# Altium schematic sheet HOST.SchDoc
size 431 x 279 mm; SheetNumber: 4; SheetTotal: 4; ENG_APP_DATE: --/--/--; DSN_APP_DATE: --/--/--; CHK_APP_DATE: --/--/--
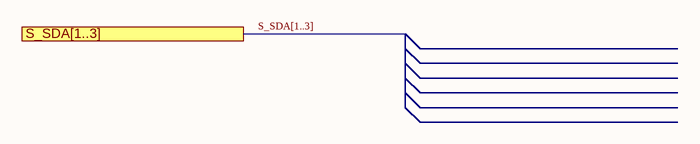
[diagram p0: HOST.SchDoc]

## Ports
S_SDA[1..3]

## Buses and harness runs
bus S_SDA[1..3] = port S_SDA[1..3]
